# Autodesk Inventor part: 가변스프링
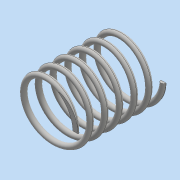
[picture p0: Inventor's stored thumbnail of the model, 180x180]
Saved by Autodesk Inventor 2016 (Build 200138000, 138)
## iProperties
Created: 2018-11
Part Number: 가변스프링
Material: 일반
Document SubType Name: Modeling
Designer: 공506_43
Density: 1 g/cm^3
Appearance: 기본값
Mass: 10.5248 g
Surface Area: 106.476 cm^2
Volume: 10.5248 cm^3
Author: 공506_43
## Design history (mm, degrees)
sketch "스케치1"
  geometry: L1 (0, 0)-(22.5, 0); L2 (22.5, 0)-(22.5, 67.25); L3 (22.5, 67.25)-(0, 67.25); L4 (0, 67.25)-(0, 0); C1 r 2 at (22.5, 0)
  constraints: 8 end point, 2 parallel, 1 centre point, 1 coincident, 1 horizontal, 1 perpendicular
  dimensions: "d0" = 22.5 distance of L2.end L3.end; "d1" = 67.25 distance of L3.end L1.start (derived); "d2" = 4 diameter of C1
feature "코일1" sketch "스케치1" pitch "d3" = 10; turns "d5" = 6; dims "d4" = 67.25 (= d1), "d6" = 0, angle "d7" = 90 deg, angle "d8" = 90 deg, "d9" = 0, "d10" = 0
sketch "스케치2"
  geometry: L1 (0, 70.18)-(67.25, 70.18); L2 (67.25, 70.18)-(67.25, -70.18); L3 (67.25, -70.18)-(0, -70.18); L4 (0, -70.18)-(0, 70.18); 3 further points
  constraints: 8 end point, 2 midpoint, 2 parallel, 1 coincident, 1 horizontal, 1 horizontal alignment, 1 perpendicular
  dimensions: "d11" = 140.35977 distance of L1.end L2.end; "d12" = 67.25 distance of L1.start L1.end (= d1)
extrude "돌출1" sketch "스케치2" stored distance "d13" = 600; taper "d14" = 0 deg
node "솔리드1"
